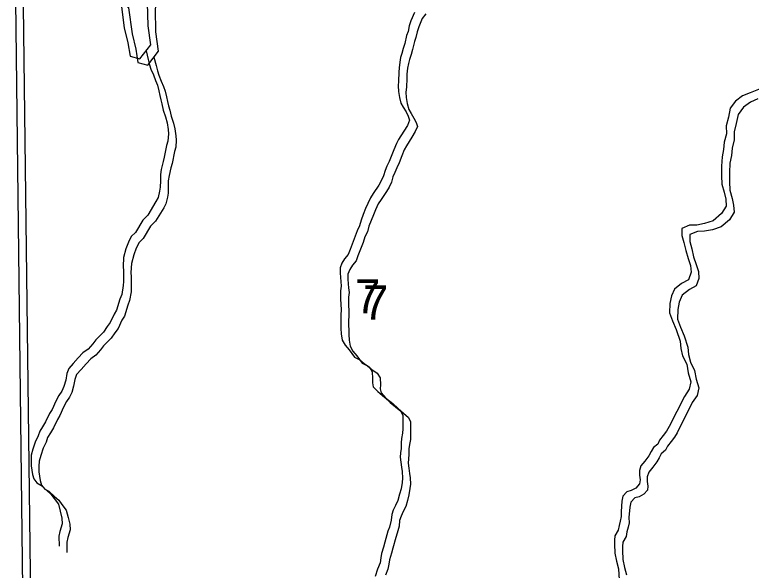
# Model space of a CAD drawing. Extents: x -21.1 to 50.3, y 0 to 22.1.
# Drawn here: x 44.094 to 44.997, y 17.935 to 18.617 of the extents above; entities that cross this region are included whole.
import ezdxf

# ---------------------------------------------------------------- set-up
doc = ezdxf.new("R2010")
doc.units = 0
for name, color, linetype in [('GM_X_Minor_Lake', 7, 'Continuous'), ('GM_X_Minor_River', 7, 'Continuous'), ('GM_X_Section', 7, 'Continuous'), ('GM_X_Section_Text', 7, 'Continuous')]:
    doc.layers.add(name, color=color, linetype=linetype)

msp = doc.modelspace()

# ---------------------------------------------------------------- linework, layer by layer
at = {"layer": 'GM_X_Minor_Lake'}
for points in [[(44.21461, 18.65156), (44.21467, 18.64283), (44.22347, 18.63265), (44.22789, 18.60043), (44.2322, 18.58186), (44.23497, 18.56556), (44.24714, 18.56224), (44.26028, 18.57943), (44.25707, 18.60294), (44.25649, 18.63102), (44.25901, 18.64812), (44.25517, 18.6553), (44.24947, 18.65564)], [(44.22425, 18.64406), (44.22431, 18.63533), (44.23311, 18.62515), (44.23752, 18.59293), (44.24183, 18.57436), (44.24461, 18.55806), (44.25677, 18.55474), (44.26992, 18.57193), (44.26671, 18.59544), (44.26612, 18.62352), (44.26865, 18.64062), (44.2648, 18.6478), (44.25911, 18.64814)]]:
    msp.add_lwpolyline(points, dxfattribs=at)
at = {"layer": 'GM_X_Minor_River'}
for points in [[(44.58378, 18.61937), (44.5793, 18.60907), (44.57745, 18.60297), (44.57599, 18.59612), (44.57413, 18.59116), (44.57193, 18.58125), (44.57008, 18.57516), (44.56823, 18.56905), (44.56675, 18.5641), (44.56566, 18.55839), (44.56496, 18.55116), (44.56463, 18.54583), (44.56434, 18.53518), (44.56363, 18.52909), (44.56407, 18.52225), (44.56527, 18.51504), (44.56723, 18.50783), (44.56993, 18.50291), (44.57341, 18.49723), (44.57611, 18.49193), (44.57767, 18.487), (44.57507, 18.48051), (44.57094, 18.47363), (44.56419, 18.46331), (44.56157, 18.45835), (44.55859, 18.45072), (44.55524, 18.44232), (44.55263, 18.43622), (44.55002, 18.43049), (44.54778, 18.42515), (44.54593, 18.41867), (44.54294, 18.41256), (44.53995, 18.40722), (44.53319, 18.39727), (44.52981, 18.39192), (44.52645, 18.38467)], [(44.59755, 18.61761), (44.59341, 18.61187), (44.58894, 18.60157), (44.58709, 18.59547), (44.58563, 18.58861), (44.58377, 18.58366), (44.58157, 18.57375), (44.57972, 18.56765), (44.57787, 18.56155), (44.57639, 18.5566), (44.5753, 18.55089), (44.5746, 18.54366), (44.57426, 18.53833), (44.57398, 18.52768), (44.57327, 18.52159), (44.5737, 18.51475), (44.57491, 18.50754), (44.57687, 18.50032), (44.57957, 18.4954), (44.58304, 18.48973), (44.58575, 18.48443), (44.58731, 18.4795), (44.58471, 18.47301), (44.58058, 18.46613), (44.57382, 18.45581), (44.5712, 18.45085), (44.56823, 18.44322), (44.56488, 18.43482), (44.56227, 18.42872), (44.55965, 18.42299), (44.55742, 18.41765), (44.55557, 18.41117), (44.55258, 18.40506), (44.54958, 18.39971), (44.54282, 18.38977), (44.53945, 18.38442), (44.53609, 18.37717)], [(44.25467, 18.57209), (44.25727, 18.56158), (44.25884, 18.55513), (44.26041, 18.54982), (44.26351, 18.54262), (44.26623, 18.5358), (44.26856, 18.53011), (44.27014, 18.52328), (44.27133, 18.51759), (44.27251, 18.51227), (44.27408, 18.50696), (44.27566, 18.49937), (44.2784, 18.49103), (44.28036, 18.48382), (44.28157, 18.47546)], [(44.2643, 18.56459), (44.2669, 18.55408), (44.26848, 18.54763), (44.27004, 18.54232), (44.27315, 18.53512), (44.27587, 18.5283), (44.2782, 18.52261), (44.27978, 18.51578), (44.28096, 18.51009), (44.28215, 18.50477), (44.28371, 18.49946), (44.2853, 18.49187), (44.28803, 18.48353), (44.29, 18.47632), (44.29121, 18.46796)], [(45.00787, 18.52577), (44.99534, 18.52077), (44.98623, 18.51691), (44.97751, 18.51041), (44.97109, 18.50164), (44.96887, 18.49061), (44.96626, 18.48034), (44.96631, 18.47046), (44.96371, 18.46019), (44.963, 18.45107), (44.96115, 18.44194), (44.96045, 18.43054), (44.96052, 18.41876), (44.96095, 18.40851), (44.96367, 18.39865), (44.96562, 18.3903), (44.96605, 18.38157), (44.96039, 18.37242), (44.95017, 18.36362), (44.93953, 18.36015), (44.93002, 18.35819), (44.92127, 18.35814), (44.91178, 18.35429), (44.91182, 18.34555), (44.91416, 18.33683), (44.9165, 18.32697), (44.9196, 18.31749), (44.92231, 18.30877), (44.92312, 18.30041), (44.91974, 18.29128), (44.91139, 18.28667), (44.90268, 18.27978), (44.89892, 18.27141), (44.89707, 18.26228), (44.89675, 18.2505), (44.90023, 18.24064), (44.90486, 18.23003), (44.90951, 18.216), (44.91032, 18.20689), (44.91266, 18.19779), (44.91766, 18.18756), (44.91963, 18.17693), (44.92273, 18.16593), (44.92088, 18.1568), (44.91484, 18.14803), (44.89634, 18.11105)], [(45.00498, 18.51326), (44.99586, 18.50941), (44.98714, 18.50291), (44.98072, 18.49414), (44.9785, 18.48311), (44.97589, 18.47283), (44.97595, 18.46296), (44.97334, 18.45269), (44.97263, 18.44357), (44.97078, 18.43444), (44.97008, 18.42304), (44.97015, 18.41126), (44.97059, 18.40101), (44.97331, 18.39115), (44.97526, 18.3828), (44.97569, 18.37407), (44.97003, 18.36492), (44.9598, 18.35612), (44.94917, 18.35264), (44.93966, 18.35069), (44.93091, 18.35064), (44.92141, 18.34679), (44.92146, 18.33805), (44.92379, 18.32933), (44.92613, 18.31946), (44.92923, 18.30999), (44.93195, 18.30126), (44.93275, 18.29291), (44.92938, 18.28378), (44.92103, 18.27917), (44.91231, 18.27228), (44.90856, 18.26391), (44.9067, 18.25478), (44.90639, 18.243), (44.90987, 18.23314), (44.9145, 18.22253), (44.91914, 18.2085), (44.91996, 18.19939), (44.92229, 18.19029), (44.9273, 18.18006), (44.92926, 18.16943), (44.93237, 18.15843), (44.93052, 18.1493), (44.92448, 18.14053), (44.90597, 18.10355)], [(44.28157, 18.47546), (44.28199, 18.47014), (44.28131, 18.46139), (44.27983, 18.45605), (44.27692, 18.44158), (44.27544, 18.43624), (44.27324, 18.42672), (44.27215, 18.42025), (44.27222, 18.41264), (44.2719, 18.40504), (44.27118, 18.40009), (44.26935, 18.39209), (44.26673, 18.38712), (44.2566, 18.37069), (44.25057, 18.36455), (44.24157, 18.34927), (44.23629, 18.34428), (44.23293, 18.33741), (44.22995, 18.3294), (44.227, 18.31873), (44.22634, 18.3077), (44.22676, 18.30238), (44.22688, 18.28907), (44.22654, 18.28412), (44.22473, 18.27308), (44.2225, 18.26736), (44.21843, 18.25402), (44.21543, 18.24905), (44.21057, 18.23874), (44.20681, 18.23377), (44.20231, 18.22689), (44.19288, 18.21769), (44.18912, 18.21271), (44.18347, 18.2062), (44.17704, 18.20159), (44.17139, 18.19546), (44.16537, 18.18856), (44.15972, 18.18243), (44.15749, 18.17633), (44.15604, 18.16795), (44.15382, 18.16033), (44.15121, 18.15461), (44.14745, 18.14925), (44.14371, 18.14237), (44.13923, 18.13207), (44.13623, 18.1271), (44.13138, 18.1168), (44.12762, 18.11068), (44.12425, 18.10533), (44.12239, 18.09961), (44.11866, 18.09198), (44.11569, 18.08321), (44.11385, 18.07597), (44.11352, 18.06988), (44.11358, 18.06304), (44.11519, 18.0524), (44.11676, 18.04671), (44.1206, 18.0418), (44.12557, 18.03918), (44.13285, 18.03277), (44.13783, 18.02825), (44.14168, 18.02296), (44.14706, 18.01578), (44.14942, 18.00705), (44.15139, 17.9987), (44.15182, 17.99186), (44.14886, 17.98233), (44.14777, 17.97662), (44.14788, 17.96407)], [(44.29121, 18.46796), (44.29163, 18.46264), (44.29095, 18.45389), (44.28947, 18.44855), (44.28655, 18.43408), (44.28508, 18.42874), (44.28287, 18.41922), (44.28179, 18.41275), (44.28185, 18.40514), (44.28154, 18.39754), (44.28082, 18.39258), (44.27899, 18.38458), (44.27637, 18.37962), (44.26624, 18.36319), (44.26021, 18.35705), (44.25121, 18.34177), (44.24593, 18.33678), (44.24257, 18.32991), (44.23959, 18.3219), (44.23664, 18.31123), (44.23597, 18.3002), (44.2364, 18.29488), (44.23651, 18.28157), (44.23617, 18.27662), (44.23437, 18.26558), (44.23213, 18.25986), (44.22806, 18.24652), (44.22506, 18.24155), (44.22021, 18.23124), (44.21645, 18.22627), (44.21194, 18.21939), (44.20252, 18.21018), (44.19876, 18.20521), (44.19311, 18.1987), (44.18668, 18.19409), (44.18103, 18.18796), (44.175, 18.18106), (44.16935, 18.17493), (44.16712, 18.16883), (44.16567, 18.16045), (44.16346, 18.15283), (44.16085, 18.14711), (44.15709, 18.14175), (44.15334, 18.13487), (44.14887, 18.12457), (44.14587, 18.1196), (44.14101, 18.1093), (44.13726, 18.10318), (44.13389, 18.09783), (44.13203, 18.09211), (44.12829, 18.08448), (44.12533, 18.07571), (44.12349, 18.06847), (44.12316, 18.06238), (44.12322, 18.05554), (44.12483, 18.0449), (44.1264, 18.03921), (44.13024, 18.0343), (44.13521, 18.03168), (44.14248, 18.02527), (44.14746, 18.02075), (44.15131, 18.01546), (44.1567, 18.00828), (44.15905, 17.99955), (44.16102, 17.9912), (44.16146, 17.98436), (44.1585, 17.97483), (44.15741, 17.96911), (44.15752, 17.95657)], [(44.52645, 18.38467), (44.52384, 18.37857), (44.52086, 18.37132), (44.51825, 18.36445), (44.51641, 18.35759), (44.51342, 18.35148), (44.5112, 18.34462), (44.50859, 18.33814), (44.50487, 18.32822), (44.50264, 18.32212), (44.49813, 18.31676), (44.49475, 18.31141), (44.49252, 18.30568), (44.49257, 18.2996), (44.493, 18.2939), (44.49342, 18.28896), (44.49385, 18.28326), (44.49314, 18.27755), (44.49322, 18.26728), (44.49365, 18.2612), (44.49371, 18.25436), (44.49338, 18.24827), (44.49353, 18.23154), (44.49396, 18.2247), (44.49517, 18.21711), (44.49864, 18.21105), (44.50363, 18.20539), (44.51017, 18.19631), (44.51667, 18.19295), (44.52203, 18.18842), (44.52853, 18.18391), (44.532, 18.17824), (44.53245, 18.16988), (44.53211, 18.16493), (44.53329, 18.16), (44.53867, 18.15396), (44.54747, 18.1468), (44.55399, 18.14077), (44.5605, 18.13512), (44.56701, 18.12985), (44.56934, 18.12455), (44.56948, 18.1082), (44.56914, 18.10287), (44.56805, 18.0964), (44.56734, 18.09107), (44.5674, 18.08422), (44.56668, 18.07889), (44.56635, 18.07357), (44.56716, 18.06749), (44.56797, 18.06103), (44.56878, 18.05571), (44.56923, 18.04773), (44.56851, 18.0424), (44.56743, 18.03479), (44.56559, 18.02793), (44.56338, 18.02031), (44.56038, 18.0142), (44.55777, 18.00847), (44.55592, 18.00313), (44.55521, 17.99628), (44.55301, 17.98752), (44.55115, 17.98256), (44.54746, 17.96922), (44.54599, 17.96312), (44.54339, 17.95512), (44.54268, 17.94979), (44.54159, 17.9437), (44.53861, 17.93607), (44.53565, 17.92692)], [(44.53609, 18.37717), (44.53348, 18.37107), (44.5305, 18.36382), (44.52789, 18.35695), (44.52605, 18.35009), (44.52306, 18.34398), (44.52083, 18.33712), (44.51823, 18.33064), (44.51451, 18.32072), (44.51228, 18.31461), (44.50776, 18.30925), (44.50439, 18.3039), (44.50215, 18.29818), (44.50221, 18.2921), (44.50263, 18.2864), (44.50306, 18.28146), (44.50349, 18.27576), (44.50277, 18.27005), (44.50286, 18.25978), (44.50329, 18.2537), (44.50335, 18.24686), (44.50302, 18.24077), (44.50316, 18.22404), (44.5036, 18.2172), (44.5048, 18.20961), (44.50828, 18.20355), (44.51327, 18.19789), (44.51981, 18.18881), (44.5263, 18.18544), (44.53166, 18.18092), (44.53817, 18.17641), (44.54164, 18.17074), (44.54209, 18.16238), (44.54175, 18.15743), (44.54293, 18.1525), (44.54831, 18.14646), (44.55711, 18.1393), (44.56363, 18.13327), (44.57014, 18.12762), (44.57665, 18.12235), (44.57897, 18.11704), (44.57911, 18.10069), (44.57878, 18.09537), (44.57769, 18.0889), (44.57697, 18.08357), (44.57703, 18.07672), (44.57632, 18.07139), (44.57598, 18.06607), (44.57679, 18.05999), (44.57761, 18.05353), (44.57841, 18.04821), (44.57886, 18.04023), (44.57815, 18.0349), (44.57707, 18.02729), (44.57523, 18.02043), (44.57301, 18.01281), (44.57002, 18.0067), (44.56741, 18.00097), (44.56555, 17.99563), (44.56485, 17.98878), (44.56264, 17.98002), (44.56078, 17.97506), (44.55709, 17.96172), (44.55562, 17.95562), (44.55303, 17.94762), (44.55232, 17.94229), (44.55123, 17.9362), (44.54825, 17.92857)], [(44.89634, 18.11105), (44.89307, 18.10551), (44.88894, 18.10015), (44.88442, 18.09441), (44.88218, 18.08945), (44.87689, 18.08522), (44.87428, 18.08026), (44.87128, 18.07529), (44.86639, 18.06878), (44.8615, 18.06266), (44.85964, 18.05694), (44.85969, 18.05124), (44.8605, 18.04554), (44.85978, 18.04059), (44.85526, 18.03561), (44.84958, 18.03252), (44.84427, 18.03096), (44.83938, 18.02559), (44.83829, 18.0195), (44.83725, 18.00695), (44.83731, 18.00048), (44.83621, 17.99515), (44.83474, 17.98943), (44.83365, 17.98372), (44.82952, 17.97684), (44.82919, 17.97152), (44.82923, 17.96657), (44.8297, 17.95555), (44.83169, 17.94568), (44.83405, 17.93657), (44.83492, 17.92289)], [(44.90597, 18.10355), (44.90271, 18.098), (44.89857, 18.09265), (44.89406, 18.08691), (44.89182, 18.08195), (44.88653, 18.07772), (44.88391, 18.07275), (44.88091, 18.06779), (44.87603, 18.06128), (44.87113, 18.05516), (44.86928, 18.04944), (44.86933, 18.04374), (44.87014, 18.03804), (44.86942, 18.03309), (44.8649, 18.02811), (44.85922, 18.02502), (44.85391, 18.02346), (44.84901, 18.01809), (44.84793, 18.012), (44.84689, 17.99944), (44.84694, 17.99298), (44.84585, 17.98765), (44.84438, 17.98193), (44.84328, 17.97622), (44.83916, 17.96934), (44.83882, 17.96402), (44.83887, 17.95907), (44.83934, 17.94805), (44.84132, 17.93818), (44.84368, 17.92907)]]:
    msp.add_lwpolyline(points, dxfattribs=at)
at = {"layer": 'GM_X_Section'}
for points in [[(44.0935, 18.71999), (45.13143, 18.72623), (45.14863, 17.70187), (44.10665, 17.68876), (44.1055, 17.74068), (44.09428, 18.66845)], [(44.10314, 18.71249), (45.14107, 18.71873), (45.15827, 17.69437), (44.11629, 17.68126), (44.11514, 17.73318), (44.10391, 18.66095)]]:
    msp.add_lwpolyline(points, close=True, dxfattribs=at)

# ---------------------------------------------------------------- texts
at = {"layer": 'GM_X_Section_Text'}
for p in [(44.51092, 18.24995), (44.52056, 18.24245)]:
    msp.add_text('7', height=0.04186, rotation=0.00001, dxfattribs=at).set_placement(p)

doc.saveas('drawing.dxf')
